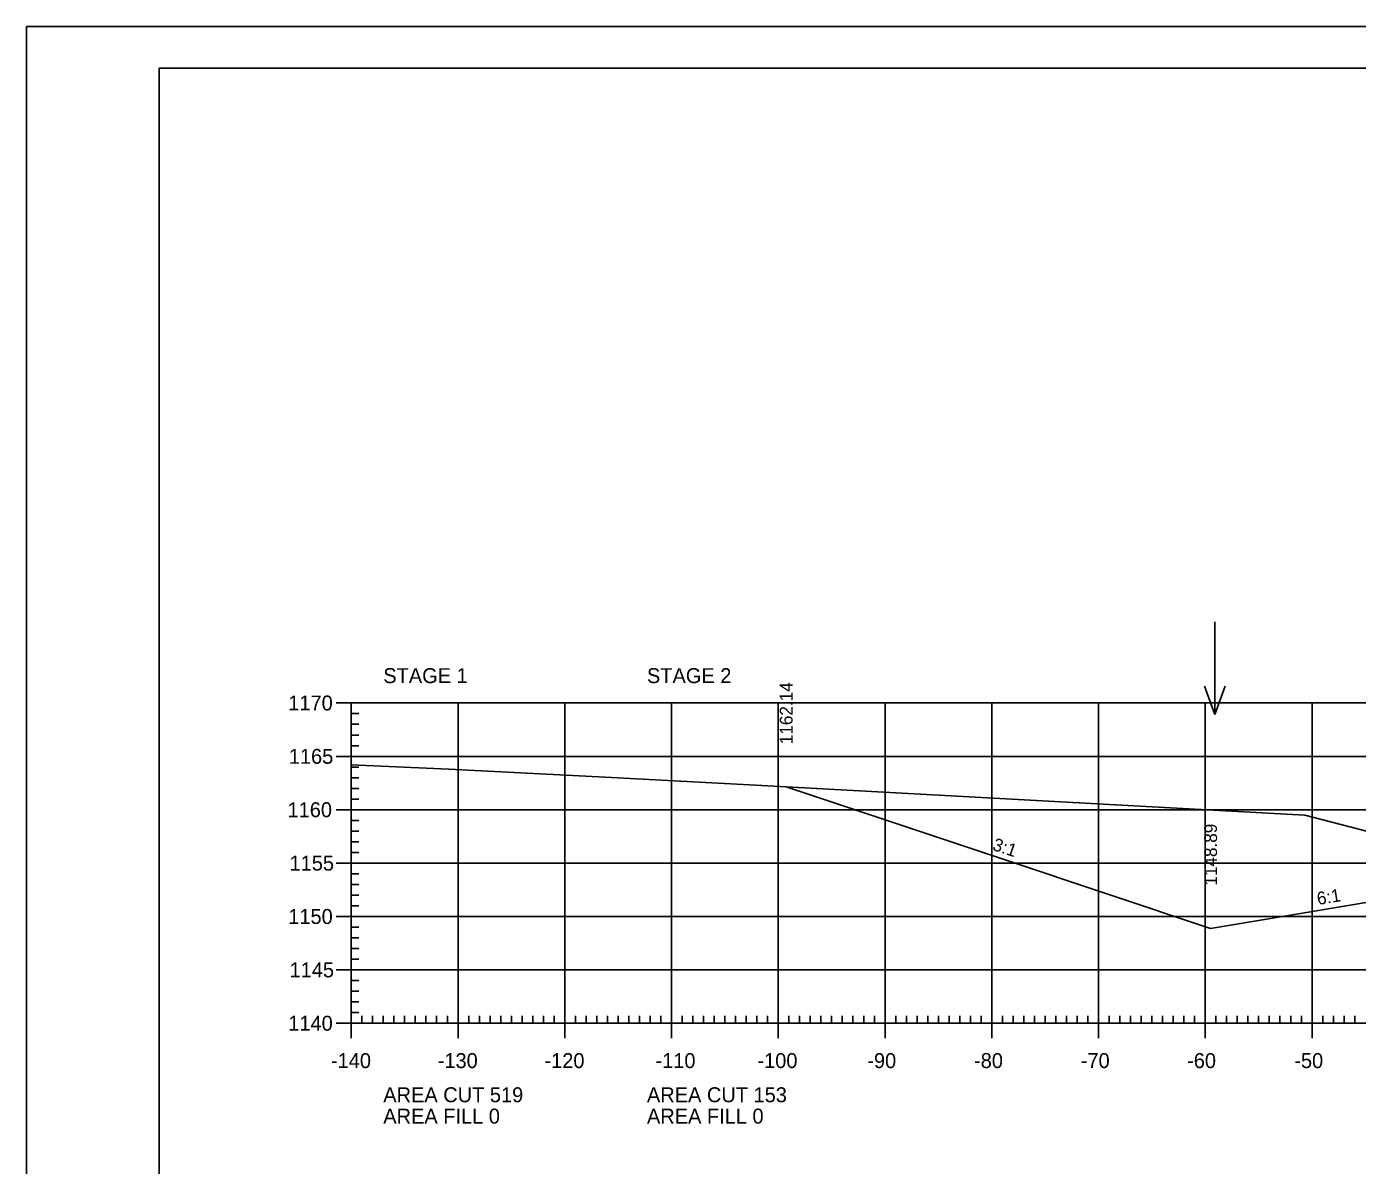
# Model space of a CAD drawing. Extents: x 1322838 to 1324533, y 339903 to 351025.
# Drawn here: x 1323533.3 to 1323658, y 341289.8 to 341396.5 of the extents above; entities that cross this region are included whole.
import ezdxf

# ---------------------------------------------------------------- set-up
doc = ezdxf.new("R2010")
doc.units = 0
for name, color, linetype in [('R_Axis', 7, 'Continuous'), ('R_Axis Annot', 7, 'Continuous'), ('R_Border', 7, 'Continuous'), ('R_Exist Surface', 7, 'Continuous'), ('R_Fin Surface', 7, 'Continuous'), ('R_Fin Surface Annot', 7, 'Continuous'), ('R_Grid', 7, 'Continuous'), ('R_No Plot', 7, 'Continuous'), ('R_Water Annot', 7, 'Continuous')]:
    doc.layers.add(name, color=color, linetype=linetype)

msp = doc.modelspace()

# ---------------------------------------------------------------- linework, layer by layer
at = {"layer": 'R_Axis'}
for p, q in [((1323562.32, 341333.13), (1323565.12, 341333.13)), ((1323563.72, 341303.13), (1323563.72, 341333.13)), ((1323563.72, 341332.13), (1323564.42, 341332.13)), ((1323563.72, 341331.13), (1323564.42, 341331.13)), ((1323563.72, 341330.13), (1323564.42, 341330.13)), ((1323562.32, 341328.13), (1323565.12, 341328.13)), ((1323563.72, 341329.13), (1323564.42, 341329.13)), ((1323563.72, 341327.13), (1323564.42, 341327.13)), ((1323563.72, 341326.13), (1323564.42, 341326.13)), ((1323563.72, 341325.13), (1323564.42, 341325.13)), ((1323562.32, 341323.13), (1323565.12, 341323.13)), ((1323563.72, 341324.13), (1323564.42, 341324.13)), ((1323563.72, 341322.13), (1323564.42, 341322.13)), ((1323563.72, 341321.13), (1323564.42, 341321.13)), ((1323563.72, 341320.13), (1323564.42, 341320.13)), ((1323562.32, 341318.13), (1323565.12, 341318.13)), ((1323563.72, 341319.13), (1323564.42, 341319.13)), ((1323563.72, 341317.13), (1323564.42, 341317.13)), ((1323563.72, 341316.13), (1323564.42, 341316.13)), ((1323563.72, 341315.13), (1323564.42, 341315.13)), ((1323562.32, 341313.13), (1323565.12, 341313.13)), ((1323563.72, 341314.13), (1323564.42, 341314.13)), ((1323563.72, 341312.13), (1323564.42, 341312.13)), ((1323563.72, 341311.13), (1323564.42, 341311.13)), ((1323563.72, 341310.13), (1323564.42, 341310.13)), ((1323562.32, 341308.13), (1323565.12, 341308.13)), ((1323563.72, 341309.13), (1323564.42, 341309.13)), ((1323563.72, 341307.13), (1323564.42, 341307.13)), ((1323563.72, 341306.13), (1323564.42, 341306.13)), ((1323563.72, 341305.13), (1323564.42, 341305.13)), ((1323563.72, 341301.73), (1323563.72, 341304.53)), ((1323573.72, 341301.73), (1323573.72, 341304.53)), ((1323583.72, 341301.73), (1323583.72, 341304.53)), ((1323593.72, 341301.73), (1323593.72, 341304.53)), ((1323603.72, 341301.73), (1323603.72, 341304.53)), ((1323613.72, 341301.73), (1323613.72, 341304.53)), ((1323623.72, 341301.73), (1323623.72, 341304.53)), ((1323633.72, 341301.73), (1323633.72, 341304.53)), ((1323643.72, 341301.73), (1323643.72, 341304.53)), ((1323653.72, 341301.73), (1323653.72, 341304.53)), ((1323562.32, 341303.13), (1323565.12, 341303.13)), ((1323563.72, 341304.13), (1323564.42, 341304.13)), ((1323563.72, 341303.13), (1323843.72, 341303.13)), ((1323564.72, 341303.13), (1323564.72, 341303.83)), ((1323565.72, 341303.13), (1323565.72, 341303.83)), ((1323566.72, 341303.13), (1323566.72, 341303.83)), ((1323567.72, 341303.13), (1323567.72, 341303.83)), ((1323568.72, 341303.13), (1323568.72, 341303.83)), ((1323569.72, 341303.13), (1323569.72, 341303.83)), ((1323570.72, 341303.13), (1323570.72, 341303.83)), ((1323571.72, 341303.13), (1323571.72, 341303.83)), ((1323572.72, 341303.13), (1323572.72, 341303.83)), ((1323574.72, 341303.13), (1323574.72, 341303.83)), ((1323575.72, 341303.13), (1323575.72, 341303.83)), ((1323576.72, 341303.13), (1323576.72, 341303.83)), ((1323577.72, 341303.13), (1323577.72, 341303.83)), ((1323578.72, 341303.13), (1323578.72, 341303.83)), ((1323579.72, 341303.13), (1323579.72, 341303.83)), ((1323580.72, 341303.13), (1323580.72, 341303.83)), ((1323581.72, 341303.13), (1323581.72, 341303.83)), ((1323582.72, 341303.13), (1323582.72, 341303.83)), ((1323584.72, 341303.13), (1323584.72, 341303.83)), ((1323585.72, 341303.13), (1323585.72, 341303.83)), ((1323586.72, 341303.13), (1323586.72, 341303.83)), ((1323587.72, 341303.13), (1323587.72, 341303.83)), ((1323588.72, 341303.13), (1323588.72, 341303.83)), ((1323589.72, 341303.13), (1323589.72, 341303.83)), ((1323590.72, 341303.13), (1323590.72, 341303.83)), ((1323591.72, 341303.13), (1323591.72, 341303.83)), ((1323592.72, 341303.13), (1323592.72, 341303.83)), ((1323594.72, 341303.13), (1323594.72, 341303.83)), ((1323595.72, 341303.13), (1323595.72, 341303.83)), ((1323596.72, 341303.13), (1323596.72, 341303.83)), ((1323597.72, 341303.13), (1323597.72, 341303.83)), ((1323598.72, 341303.13), (1323598.72, 341303.83)), ((1323599.72, 341303.13), (1323599.72, 341303.83)), ((1323600.72, 341303.13), (1323600.72, 341303.83)), ((1323601.72, 341303.13), (1323601.72, 341303.83)), ((1323602.72, 341303.13), (1323602.72, 341303.83)), ((1323604.72, 341303.13), (1323604.72, 341303.83)), ((1323605.72, 341303.13), (1323605.72, 341303.83)), ((1323606.72, 341303.13), (1323606.72, 341303.83)), ((1323607.72, 341303.13), (1323607.72, 341303.83)), ((1323608.72, 341303.13), (1323608.72, 341303.83)), ((1323609.72, 341303.13), (1323609.72, 341303.83)), ((1323610.72, 341303.13), (1323610.72, 341303.83)), ((1323611.72, 341303.13), (1323611.72, 341303.83)), ((1323612.72, 341303.13), (1323612.72, 341303.83)), ((1323614.72, 341303.13), (1323614.72, 341303.83)), ((1323615.72, 341303.13), (1323615.72, 341303.83)), ((1323616.72, 341303.13), (1323616.72, 341303.83)), ((1323617.72, 341303.13), (1323617.72, 341303.83)), ((1323618.72, 341303.13), (1323618.72, 341303.83)), ((1323619.72, 341303.13), (1323619.72, 341303.83)), ((1323620.72, 341303.13), (1323620.72, 341303.83)), ((1323621.72, 341303.13), (1323621.72, 341303.83)), ((1323622.72, 341303.13), (1323622.72, 341303.83)), ((1323624.72, 341303.13), (1323624.72, 341303.83)), ((1323625.72, 341303.13), (1323625.72, 341303.83)), ((1323626.72, 341303.13), (1323626.72, 341303.83)), ((1323627.72, 341303.13), (1323627.72, 341303.83)), ((1323628.72, 341303.13), (1323628.72, 341303.83)), ((1323629.72, 341303.13), (1323629.72, 341303.83)), ((1323630.72, 341303.13), (1323630.72, 341303.83)), ((1323631.72, 341303.13), (1323631.72, 341303.83)), ((1323632.72, 341303.13), (1323632.72, 341303.83)), ((1323634.72, 341303.13), (1323634.72, 341303.83)), ((1323635.72, 341303.13), (1323635.72, 341303.83)), ((1323636.72, 341303.13), (1323636.72, 341303.83)), ((1323637.72, 341303.13), (1323637.72, 341303.83)), ((1323638.72, 341303.13), (1323638.72, 341303.83)), ((1323639.72, 341303.13), (1323639.72, 341303.83)), ((1323640.72, 341303.13), (1323640.72, 341303.83)), ((1323641.72, 341303.13), (1323641.72, 341303.83)), ((1323642.72, 341303.13), (1323642.72, 341303.83)), ((1323644.72, 341303.13), (1323644.72, 341303.83)), ((1323645.72, 341303.13), (1323645.72, 341303.83)), ((1323646.72, 341303.13), (1323646.72, 341303.83)), ((1323647.72, 341303.13), (1323647.72, 341303.83)), ((1323648.72, 341303.13), (1323648.72, 341303.83)), ((1323649.72, 341303.13), (1323649.72, 341303.83)), ((1323650.72, 341303.13), (1323650.72, 341303.83)), ((1323651.72, 341303.13), (1323651.72, 341303.83)), ((1323652.72, 341303.13), (1323652.72, 341303.83)), ((1323654.72, 341303.13), (1323654.72, 341303.83)), ((1323655.72, 341303.13), (1323655.72, 341303.83)), ((1323656.72, 341303.13), (1323656.72, 341303.83)), ((1323657.72, 341303.13), (1323657.72, 341303.83))]:
    msp.add_line(p, q, dxfattribs=at)
at = {"layer": 'R_Border'}
for p, q in [((1323545.72, 341392.59), (1323861.9, 341392.59)), ((1323545.72, 341187.13), (1323545.72, 341392.59))]:
    msp.add_line(p, q, dxfattribs=at)
at = {"layer": 'R_Exist Surface'}
msp.add_lwpolyline([(1323563.72, 341327.35), (1323572.87, 341326.92), (1323586.91, 341326.21), (1323601.04, 341325.46), (1323653.06, 341322.62), (1323660.65, 341320.66)], dxfattribs=at)
at = {"layer": 'R_Fin Surface'}
msp.add_lwpolyline([(1323604.46, 341325.27), (1323604.46, 341325.27), (1323624.97, 341318.43), (1323644.21, 341312.02), (1323644.22, 341312.02), (1323650.78, 341313.11), (1323658.22, 341314.35), (1323661.42, 341314.89), (1323666.22, 341315.68), (1323672.22, 341315.92), (1323674.22, 341315.96), (1323703.72, 341316.55), (1323722.27, 341316.18), (1323733.22, 341315.96), (1323735.22, 341315.92), (1323741.22, 341315.68), (1323746.01, 341314.89), (1323749.21, 341314.35), (1323756.66, 341313.11), (1323763.22, 341312.02), (1323767.07, 341313.3), (1323772.91, 341315.25)], dxfattribs=at)
at = {"layer": 'R_Grid'}
for p, q in [((1323563.72, 341333.13), (1323843.72, 341333.13)), ((1323563.72, 341303.13), (1323563.72, 341333.13)), ((1323573.72, 341303.13), (1323573.72, 341333.13)), ((1323583.72, 341303.13), (1323583.72, 341333.13)), ((1323593.72, 341303.13), (1323593.72, 341333.13)), ((1323603.72, 341303.13), (1323603.72, 341333.13)), ((1323613.72, 341303.13), (1323613.72, 341333.13)), ((1323623.72, 341303.13), (1323623.72, 341333.13)), ((1323633.72, 341303.13), (1323633.72, 341333.13)), ((1323643.72, 341303.13), (1323643.72, 341333.13)), ((1323653.72, 341303.13), (1323653.72, 341333.13)), ((1323563.72, 341328.13), (1323843.72, 341328.13)), ((1323563.72, 341323.13), (1323843.72, 341323.13)), ((1323563.72, 341318.13), (1323843.72, 341318.13)), ((1323563.72, 341313.13), (1323843.72, 341313.13)), ((1323563.72, 341308.13), (1323843.72, 341308.13)), ((1323563.72, 341303.13), (1323843.72, 341303.13))]:
    msp.add_line(p, q, dxfattribs=at)
at = {"layer": 'R_No Plot'}
msp.add_line((1323533.31, 341396.49), (1323866.65, 341396.49), dxfattribs=at)
for points in [[(1323533.31, 341396.49), (1323866.65, 341396.49), (1323866.65, 341183.15), (1323533.31, 341183.15)], [(1323779.64, 341392.59), (1323799.26, 341392.59), (1323799.26, 341382.71), (1323815.37, 341382.71), (1323838.57, 341382.71), (1323838.57, 341350.04), (1323861.77, 341350.04), (1323861.9, 341187.13), (1323545.72, 341187.13), (1323545.72, 341392.59)]]:
    msp.add_lwpolyline(points, close=True, dxfattribs=at)
msp.add_lwpolyline([(1323658.22, 341314.35), (1323650.78, 341313.11), (1323644.22, 341312.02), (1323644.21, 341312.02), (1323624.97, 341318.43), (1323604.46, 341325.27), (1323604.46, 341325.27), (1323653.06, 341322.62), (1323660.65, 341320.66)], dxfattribs=at)
at = {"layer": 'R_Water Annot'}
for p, q in [((1323644.61, 341340.74), (1323644.61, 341332.04)), ((1323644.61, 341332.04), (1323643.64, 341334.7)), ((1323644.61, 341332.04), (1323645.58, 341334.7))]:
    msp.add_line(p, q, dxfattribs=at)

# ---------------------------------------------------------------- texts
at = {"layer": 'R_Axis Annot'}
for s, p in [('STAGE 1', (1323566.72, 341334.99)), ('STAGE 2', (1323591.42, 341334.99)), ('1170', (1323557.82, 341332.43)), ('1165', (1323557.87, 341327.43)), ('1160', (1323557.75, 341322.43)), ('1155', (1323557.94, 341317.43)), ('1150', (1323557.82, 341312.43)), ('1145', (1323557.94, 341307.43)), ('1140', (1323557.82, 341302.43)), ('-140', (1323561.82, 341298.93)), ('-130', (1323571.82, 341298.93)), ('-120', (1323581.82, 341298.93)), ('-110', (1323592.22, 341298.93)), ('-100', (1323601.77, 341298.93)), ('-90', (1323612.06, 341298.93)), ('-80', (1323622.06, 341298.93)), ('-70', (1323632.06, 341298.93)), ('-60', (1323642.02, 341298.93)), ('-50', (1323652.06, 341298.93)), ('AREA CUT 519', (1323566.72, 341295.73)), ('AREA CUT 153', (1323591.42, 341295.73)), ('AREA FILL 0', (1323566.72, 341293.73)), ('AREA FILL 0', (1323591.42, 341293.73))]:
    msp.add_text(s, height=1.4, dxfattribs=at).set_placement(p)
at = {"layer": 'R_Fin Surface Annot'}
for s, rotation, p in [('1162.14', 90, (1323605.06, 341329.27)), ('1148.89', 90, (1323644.82, 341316.02)), ('3:1', 341.5651, (1323623.71, 341319.38)), ('6:1', 9.4606, (1323654.28, 341314.2))]:
    msp.add_text(s, height=1.2, rotation=rotation, dxfattribs=at).set_placement(p)

doc.saveas('drawing.dxf')
